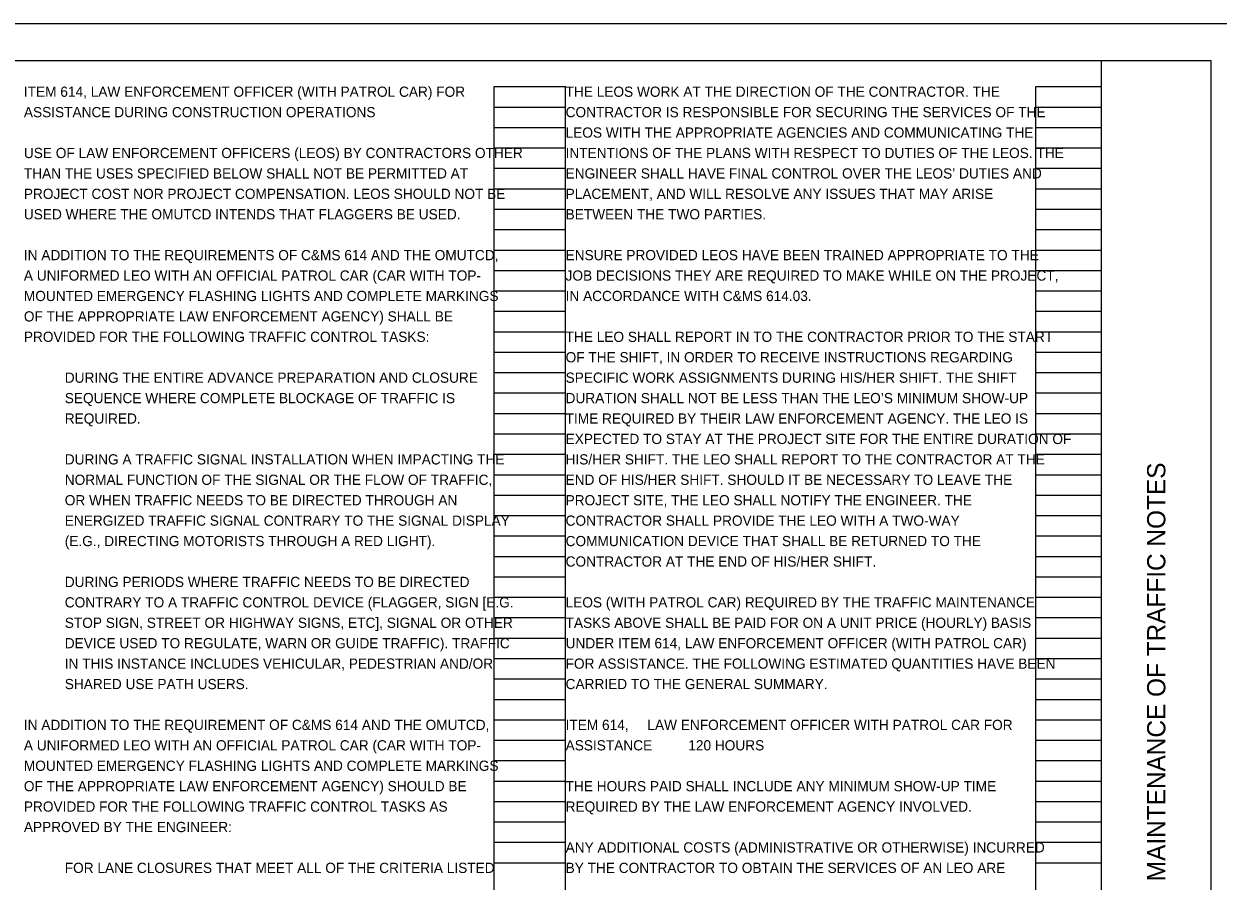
# Model space of a CAD drawing. Extents: x 0 to 50.5, y 0 to 22.
# Drawn here: x 17.24 to 33.6, y 10.25 to 22 of the extents above; entities that cross this region are included whole.
import ezdxf

# ---------------------------------------------------------------- set-up
doc = ezdxf.new("R2010")
doc.units = 0
for name, color, linetype in [('SH_Border', 7, 'Continuous'), ('SH_Cut_Line', 7, 'Continuous'), ('SH_Data', 7, 'Continuous'), ('SH_Text', 7, 'Continuous')]:
    doc.layers.add(name, color=color, linetype=linetype)

msp = doc.modelspace()

# ---------------------------------------------------------------- linework, layer by layer
at = {"layer": 'SH_Border'}
msp.add_line((32, 0.5), (32, 21.5), dxfattribs=at)
msp.add_lwpolyline([(1.5, 21.5), (33.5, 21.5), (33.5, 0.5), (1.5, 0.5)], close=True, dxfattribs=at)
at = {"layer": 'SH_Cut_Line'}
msp.add_lwpolyline([(0, 0), (34, 0), (34, 22), (0, 22)], close=True, dxfattribs=at)
at = {"layer": 'SH_Data'}
for p, q in [((23.68, 0.98), (23.68, 21.14)), ((23.68, 21.14), (24.66, 21.14)), ((24.66, 0.98), (24.66, 21.14)), ((31.1, 0.98), (31.1, 21.14)), ((31.1, 21.14), (32, 21.14)), ((32, 0.98), (32, 21.14)), ((23.68, 20.86), (24.66, 20.86)), ((31.1, 20.86), (32, 20.86)), ((23.68, 20.58), (24.66, 20.58)), ((31.1, 20.58), (32, 20.58)), ((23.68, 20.3), (24.66, 20.3)), ((31.1, 20.3), (32, 20.3)), ((23.68, 20.02), (24.66, 20.02)), ((31.1, 20.02), (32, 20.02)), ((23.68, 19.74), (24.66, 19.74)), ((31.1, 19.74), (32, 19.74)), ((23.68, 19.46), (24.66, 19.46)), ((31.1, 19.46), (32, 19.46)), ((23.68, 19.18), (24.66, 19.18)), ((31.1, 19.18), (32, 19.18)), ((23.68, 18.9), (24.66, 18.9)), ((31.1, 18.9), (32, 18.9)), ((23.68, 18.62), (24.66, 18.62)), ((31.1, 18.62), (32, 18.62)), ((23.68, 18.34), (24.66, 18.34)), ((31.1, 18.34), (32, 18.34)), ((23.68, 18.06), (24.66, 18.06)), ((31.1, 18.06), (32, 18.06)), ((23.68, 17.78), (24.66, 17.78)), ((31.1, 17.78), (32, 17.78)), ((23.68, 17.5), (24.66, 17.5)), ((31.1, 17.5), (32, 17.5)), ((23.68, 17.22), (24.66, 17.22)), ((31.1, 17.22), (32, 17.22)), ((23.68, 16.94), (24.66, 16.94)), ((31.1, 16.94), (32, 16.94)), ((23.68, 16.66), (24.66, 16.66)), ((31.1, 16.66), (32, 16.66)), ((23.68, 16.38), (24.66, 16.38)), ((31.1, 16.38), (32, 16.38)), ((23.68, 16.1), (24.66, 16.1)), ((31.1, 16.1), (32, 16.1)), ((23.68, 15.82), (24.66, 15.82)), ((31.1, 15.82), (32, 15.82)), ((23.68, 15.54), (24.66, 15.54)), ((31.1, 15.54), (32, 15.54)), ((23.68, 15.26), (24.66, 15.26)), ((31.1, 15.26), (32, 15.26)), ((23.68, 14.98), (24.66, 14.98)), ((31.1, 14.98), (32, 14.98)), ((23.68, 14.7), (24.66, 14.7)), ((31.1, 14.7), (32, 14.7)), ((23.68, 14.42), (24.66, 14.42)), ((31.1, 14.42), (32, 14.42)), ((23.68, 14.14), (24.66, 14.14)), ((31.1, 14.14), (32, 14.14)), ((23.68, 13.86), (24.66, 13.86)), ((31.1, 13.86), (32, 13.86)), ((23.68, 13.58), (24.66, 13.58)), ((31.1, 13.58), (32, 13.58)), ((23.68, 13.3), (24.66, 13.3)), ((31.1, 13.3), (32, 13.3)), ((23.68, 13.02), (24.66, 13.02)), ((31.1, 13.02), (32, 13.02)), ((23.68, 12.74), (24.66, 12.74)), ((31.1, 12.74), (32, 12.74)), ((23.68, 12.46), (24.66, 12.46)), ((31.1, 12.46), (32, 12.46)), ((23.68, 12.18), (24.66, 12.18)), ((31.1, 12.18), (32, 12.18)), ((23.68, 11.9), (24.66, 11.9)), ((31.1, 11.9), (32, 11.9)), ((23.68, 11.62), (24.66, 11.62)), ((31.1, 11.62), (32, 11.62)), ((23.68, 11.34), (24.66, 11.34)), ((31.1, 11.34), (32, 11.34)), ((23.68, 11.06), (24.66, 11.06)), ((31.1, 11.06), (32, 11.06)), ((23.68, 10.78), (24.66, 10.78)), ((31.1, 10.78), (32, 10.78)), ((23.68, 10.5), (24.66, 10.5)), ((31.1, 10.5), (32, 10.5))]:
    msp.add_line(p, q, dxfattribs=at)

# ---------------------------------------------------------------- texts
msp.add_text('MAINTENANCE OF TRAFFIC NOTES', height=0.25, rotation=90, dxfattribs=at).set_placement((32.875, 10.247))
at = {"layer": 'SH_Text'}
for s, p in [('ITEM 614, LAW ENFORCEMENT OFFICER (WITH PATROL CAR) FOR ', (17.24, 21)), ('THE LEOS WORK AT THE DIRECTION OF THE CONTRACTOR. THE ', (24.66, 21)), ('ASSISTANCE DURING CONSTRUCTION OPERATIONS', (17.24, 20.72)), ('CONTRACTOR IS RESPONSIBLE FOR SECURING THE SERVICES OF THE ', (24.66, 20.72)), ('LEOS WITH THE APPROPRIATE AGENCIES AND COMMUNICATING THE ', (24.66, 20.44)), ('USE OF LAW ENFORCEMENT OFFICERS (LEOS) BY CONTRACTORS OTHER ', (17.24, 20.16)), ('INTENTIONS OF THE PLANS WITH RESPECT TO DUTIES OF THE LEOS. THE ', (24.66, 20.16)), ('THAN THE USES SPECIFIED BELOW SHALL NOT BE PERMITTED AT ', (17.24, 19.88)), ('ENGINEER SHALL HAVE FINAL CONTROL OVER THE LEOS’ DUTIES AND ', (24.66, 19.88)), ('PROJECT COST NOR PROJECT COMPENSATION. LEOS SHOULD NOT BE ', (17.24, 19.6)), ('PLACEMENT, AND WILL RESOLVE ANY ISSUES THAT MAY ARISE ', (24.66, 19.6)), ('USED WHERE THE OMUTCD INTENDS THAT FLAGGERS BE USED. ', (17.24, 19.32)), ('BETWEEN THE TWO PARTIES. ', (24.66, 19.32)), ('IN ADDITION TO THE REQUIREMENTS OF C&MS 614 AND THE OMUTCD, ', (17.24, 18.76)), ('ENSURE PROVIDED LEOS HAVE BEEN TRAINED APPROPRIATE TO THE ', (24.66, 18.76)), ('A UNIFORMED LEO WITH AN OFFICIAL PATROL CAR (CAR WITH TOP-', (17.24, 18.48)), ('JOB DECISIONS THEY ARE REQUIRED TO MAKE WHILE ON THE PROJECT, ', (24.66, 18.48)), ('MOUNTED EMERGENCY FLASHING LIGHTS AND COMPLETE MARKINGS ', (17.24, 18.2)), ('IN ACCORDANCE WITH C&MS 614.03.', (24.66, 18.2)), ('OF THE APPROPRIATE LAW ENFORCEMENT AGENCY) SHALL BE ', (17.24, 17.92)), ('PROVIDED FOR THE FOLLOWING TRAFFIC CONTROL TASKS:', (17.24, 17.64)), ('THE LEO SHALL REPORT IN TO THE CONTRACTOR PRIOR TO THE START ', (24.66, 17.64)), ('OF THE SHIFT, IN ORDER TO RECEIVE INSTRUCTIONS REGARDING ', (24.66, 17.36)), ('DURING THE ENTIRE ADVANCE PREPARATION AND CLOSURE ', (17.8, 17.08)), ('SPECIFIC WORK ASSIGNMENTS DURING HIS/HER SHIFT. THE SHIFT ', (24.66, 17.08)), ('SEQUENCE WHERE COMPLETE BLOCKAGE OF TRAFFIC IS ', (17.8, 16.8)), ('DURATION SHALL NOT BE LESS THAN THE LEO’S MINIMUM SHOW-UP ', (24.66, 16.8)), ('REQUIRED.', (17.8, 16.52)), ('TIME REQUIRED BY THEIR LAW ENFORCEMENT AGENCY. THE LEO IS ', (24.66, 16.52)), ('EXPECTED TO STAY AT THE PROJECT SITE FOR THE ENTIRE DURATION OF ', (24.66, 16.24)), ('DURING A TRAFFIC SIGNAL INSTALLATION WHEN IMPACTING THE ', (17.8, 15.96)), ('HIS/HER SHIFT. THE LEO SHALL REPORT TO THE CONTRACTOR AT THE ', (24.66, 15.96)), ('NORMAL FUNCTION OF THE SIGNAL OR THE FLOW OF TRAFFIC, ', (17.8, 15.68)), ('END OF HIS/HER SHIFT. SHOULD IT BE NECESSARY TO LEAVE THE ', (24.66, 15.68)), ('OR WHEN TRAFFIC NEEDS TO BE DIRECTED THROUGH AN ', (17.8, 15.4)), ('PROJECT SITE, THE LEO SHALL NOTIFY THE ENGINEER. THE ', (24.66, 15.4)), ('ENERGIZED TRAFFIC SIGNAL CONTRARY TO THE SIGNAL DISPLAY ', (17.8, 15.12)), ('CONTRACTOR SHALL PROVIDE THE LEO WITH A TWO-WAY ', (24.66, 15.12)), ('(E.G., DIRECTING MOTORISTS THROUGH A RED LIGHT).', (17.8, 14.84)), ('COMMUNICATION DEVICE THAT SHALL BE RETURNED TO THE ', (24.66, 14.84)), ('CONTRACTOR AT THE END OF HIS/HER SHIFT. ', (24.66, 14.56)), ('DURING PERIODS WHERE TRAFFIC NEEDS TO BE DIRECTED ', (17.8, 14.28)), ('CONTRARY TO A TRAFFIC CONTROL DEVICE (FLAGGER, SIGN [E.G. ', (17.8, 14)), ('LEOS (WITH PATROL CAR) REQUIRED BY THE TRAFFIC MAINTENANCE ', (24.66, 14)), ('STOP SIGN, STREET OR HIGHWAY SIGNS, ETC], SIGNAL OR OTHER ', (17.8, 13.72)), ('TASKS ABOVE SHALL BE PAID FOR ON A UNIT PRICE (HOURLY) BASIS ', (24.66, 13.72)), ('DEVICE USED TO REGULATE, WARN OR GUIDE TRAFFIC). TRAFFIC ', (17.8, 13.44)), ('UNDER ITEM 614, LAW ENFORCEMENT OFFICER (WITH PATROL CAR) ', (24.66, 13.44)), ('IN THIS INSTANCE INCLUDES VEHICULAR, PEDESTRIAN AND/OR ', (17.8, 13.16)), ('FOR ASSISTANCE. THE FOLLOWING ESTIMATED QUANTITIES HAVE BEEN ', (24.66, 13.16)), ('SHARED USE PATH USERS.', (17.8, 12.88)), ('CARRIED TO THE GENERAL SUMMARY.', (24.66, 12.88)), ('IN ADDITION TO THE REQUIREMENT OF C&MS 614 AND THE OMUTCD, ', (17.24, 12.32)), ('ITEM 614,  ', (24.66, 12.32)), ('LAW ENFORCEMENT OFFICER WITH PATROL CAR FOR ', (25.78, 12.32)), ('A UNIFORMED LEO WITH AN OFFICIAL PATROL CAR (CAR WITH TOP-', (17.24, 12.04)), ('ASSISTANCE ', (24.66, 12.04)), ('120 HOURS', (26.34, 12.04)), ('MOUNTED EMERGENCY FLASHING LIGHTS AND COMPLETE MARKINGS ', (17.24, 11.76)), ('OF THE APPROPRIATE LAW ENFORCEMENT AGENCY) SHOULD BE ', (17.24, 11.48)), ('THE HOURS PAID SHALL INCLUDE ANY MINIMUM SHOW-UP TIME ', (24.66, 11.48)), ('PROVIDED FOR THE FOLLOWING TRAFFIC CONTROL TASKS AS ', (17.24, 11.2)), ('REQUIRED BY THE LAW ENFORCEMENT AGENCY INVOLVED.', (24.66, 11.2)), ('APPROVED BY THE ENGINEER:', (17.24, 10.92)), ('ANY ADDITIONAL COSTS (ADMINISTRATIVE OR OTHERWISE) INCURRED ', (24.66, 10.64)), ('FOR LANE CLOSURES THAT MEET ALL OF THE CRITERIA LISTED ', (17.8, 10.36)), ('BY THE CONTRACTOR TO OBTAIN THE SERVICES OF AN LEO ARE ', (24.66, 10.36))]:
    msp.add_text(s, height=0.14, dxfattribs=at).set_placement(p)

doc.saveas('drawing.dxf')
